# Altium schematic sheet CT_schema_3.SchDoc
size 152 x 123 mm
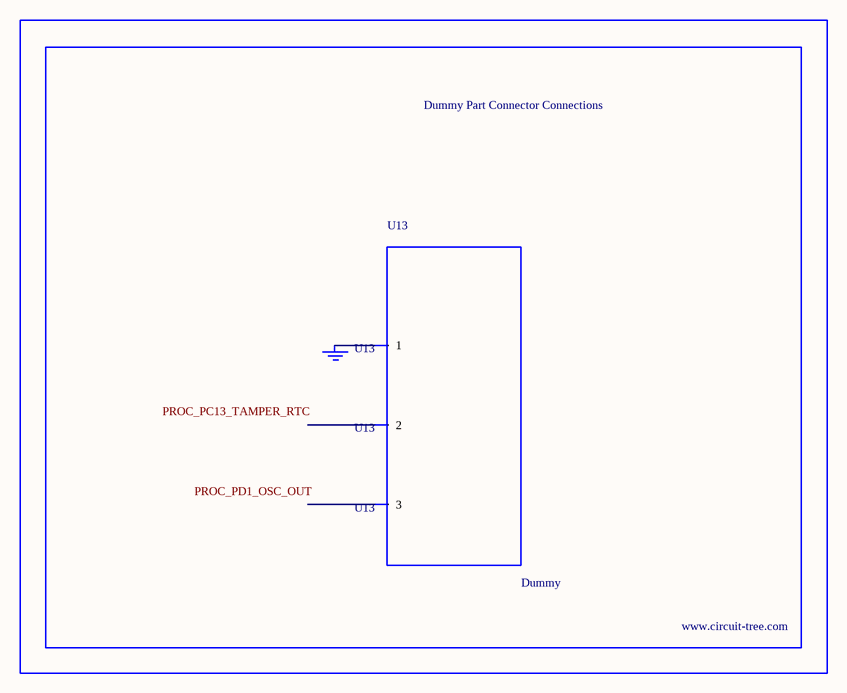
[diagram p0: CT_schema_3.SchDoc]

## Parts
BORDER2  (no value)
GND_INSTANCE_2_0  (no value)
U13  Dummy  [DUMMY_PACKAGE_103]

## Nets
NetGND_INSTANCE_2_0_0: GND_INSTANCE_2_0.0(GND) U13.1

Not connected (* = marked no-connect by the designer): U13 2 3

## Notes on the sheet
- Labels drawn without touching a wire or pin: PROC_PC13_TAMPER_RTC, PROC_PD1_OSC_OUT

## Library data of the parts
BORDER2 = BORDER_PAGE2
GND_INSTANCE_2_0 = GND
